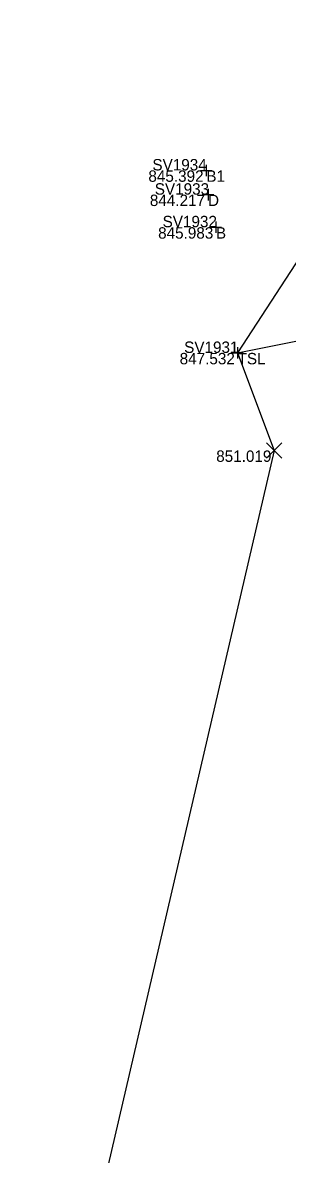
# Model space of a CAD drawing. Extents: x 2125299 to 2129212, y 713100 to 714300.
# Drawn here: x 2127358.1 to 2127381.3, y 713883.9 to 713983.1 of the extents above; entities that cross this region are included whole.
import ezdxf

# ---------------------------------------------------------------- set-up
doc = ezdxf.new("R2010")
doc.units = 0
for name, color, linetype in [('DR_X_Ditch', 7, 'Continuous'), ('DT_X_Terrain_Boundary', 7, 'Continuous'), ('RW_P_Esmt_TMP', 7, 'Continuous'), ('RW_X_Esmt_CH', 7, 'Continuous'), ('RW_X_Fee_WL', 7, 'Continuous'), ('SV_X_Break_Lines', 7, 'Continuous'), ('SV_X_Mon_Cells_Found', 7, 'Continuous'), ('SV_X_Text_Elevation', 7, 'Continuous'), ('SV_X_Toe_of_Slope', 7, 'Continuous')]:
    doc.layers.add(name, color=color, linetype=linetype)

msp = doc.modelspace()

# ---------------------------------------------------------------- linework, layer by layer
at = {"layer": 'DR_X_Ditch'}
msp.add_line((2127374.321, 713968.066), (2127374.321, 713968.066), dxfattribs=at)
at = {"layer": 'DT_X_Terrain_Boundary'}
msp.add_lwpolyline([(2127395.42, 713982.633), (2127376.912, 713954.189), (2127380.124, 713945.637), (2127358.084, 713850.693)], dxfattribs=at)
at = {"layer": 'SV_X_Break_Lines'}
for p, q in [((2127374.172, 713970.189), (2127374.172, 713970.189)), ((2127375.015, 713965.208), (2127375.015, 713965.208))]:
    msp.add_line(p, q, dxfattribs=at)
at = {"layer": 'SV_X_Mon_Cells_Found'}
for p, q in [((2127373.672, 713970.189), (2127374.672, 713970.189)), ((2127374.172, 713970.689), (2127374.172, 713969.689)), ((2127374.172, 713970.189), (2127374.172, 713970.189)), ((2127374.321, 713968.566), (2127374.321, 713967.566)), ((2127373.821, 713968.066), (2127374.821, 713968.066)), ((2127374.321, 713968.066), (2127374.321, 713968.066)), ((2127374.515, 713965.208), (2127375.515, 713965.208)), ((2127375.015, 713965.708), (2127375.015, 713964.708)), ((2127375.015, 713965.208), (2127375.015, 713965.208)), ((2127376.912, 713954.689), (2127376.912, 713953.689)), ((2127376.412, 713954.189), (2127377.412, 713954.189)), ((2127376.912, 713954.189), (2127376.912, 713954.189))]:
    msp.add_line(p, q, dxfattribs=at)
at = {"layer": 'SV_X_Text_Elevation'}
for p, q in [((2127379.457, 713944.97), (2127380.79, 713946.305)), ((2127379.457, 713946.305), (2127380.79, 713944.97))]:
    msp.add_line(p, q, dxfattribs=at)
at = {"layer": 'SV_X_Toe_of_Slope'}
msp.add_lwpolyline([(2127376.912, 713954.189), (2127469.559, 713972.72), (2127513.706, 713979.781), (2127526.759, 713983.146)], dxfattribs=at)

# ---------------------------------------------------------------- texts
at = {"layer": 'RW_P_Esmt_TMP'}
for s, p in [('B1', (2127374.172, 713969.189)), ('D', (2127374.321, 713967.066)), ('B', (2127375.015, 713964.208)), ('TSL', (2127376.912, 713953.189))]:
    msp.add_text(s, height=1, dxfattribs=at).set_placement(p)
at = {"layer": 'RW_X_Esmt_CH'}
for s, p in [('SV1934', (2127369.451, 713970.189)), ('SV1933', (2127369.659, 713968.066)), ('SV1932', (2127370.344, 713965.208)), ('SV1931', (2127372.232, 713954.189))]:
    msp.add_text(s, height=1, dxfattribs=at).set_placement(p)
at = {"layer": 'RW_X_Fee_WL'}
for s, p in [('845.392', (2127369.098, 713969.189)), ('844.217', (2127369.225, 713967.066)), ('845.983', (2127369.951, 713964.208)), ('847.532', (2127371.839, 713953.189)), ('851.019', (2127375.04, 713944.637))]:
    msp.add_text(s, height=1, dxfattribs=at).set_placement(p)

doc.saveas('drawing.dxf')
